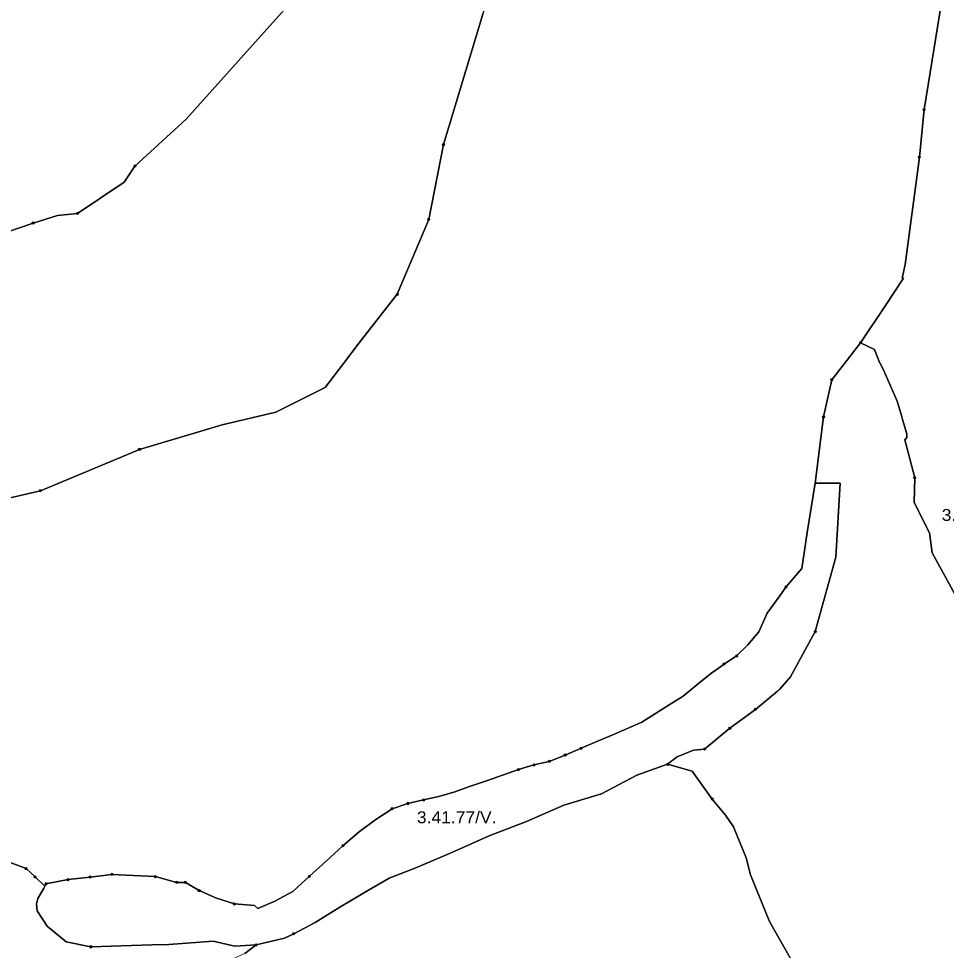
# Model space of a CAD drawing. Extents: x -650455 to -642254, y -1075222 to -1066610.
# Drawn here: x -646705 to -645923, y -1070494 to -1069709 of the extents above; entities that cross this region are included whole.
import ezdxf
from ezdxf.enums import TextEntityAlignment as Align

# ---------------------------------------------------------------- set-up
doc = ezdxf.new("R2010")
doc.units = 0
doc.header["$LTSCALE"] = 4
doc.header["$PDMODE"] = 32
doc.header["$PDSIZE"] = 2
for name, color, linetype, lineweight in [('1', 7, 'Continuous', 25), ('11', 7, 'Continuous', 13), ('12', 7, 'Continuous', 13), ('13', 7, 'Continuous', 13), ('14', 7, 'Continuous', 13), ('15', 7, 'Continuous', 13)]:
    doc.layers.add(name, color=color, linetype=linetype, lineweight=lineweight)
doc.layers.add('2', color=7, linetype='Continuous')

msp = doc.modelspace()

# ---------------------------------------------------------------- linework, layer by layer
at = {"layer": '1'}
for points in [[(-646385.5, -1069941.501), (-646359, -1069878.5), (-646346.5, -1069815.501), (-646313.5, -1069705.501), (-646295.5, -1069658.001), (-646241.5, -1069496.001), (-646193.5, -1069374.501), (-646167.5, -1069296), (-646158, -1069244.001), (-646160.5, -1069203.501), (-646183.5, -1069131.501), (-646202, -1069077.5), (-646206, -1069050.501), (-646201.5, -1069028), (-646192, -1069010.001), (-646156, -1068987.5), (-646026.5, -1068930.5), (-646006.5, -1068918.5), (-645969.5, -1068908.001), (-645923, -1068902.5)], [(-645960, -1069928), (-645957.5, -1069916.501), (-645945.5, -1069826), (-645941.5, -1069786), (-645925, -1069683.5), (-645928.5, -1069687.5), (-645921.5, -1069660.5), (-645908.5, -1069548.001), (-645886.5, -1069492.001), (-645856.5, -1069447.001), (-645698.133, -1069270.881), (-645694.109, -1069269.277), (-645694.125, -1069269.251), (-645637, -1069246.5), (-645633.75, -1069245.251), (-645633.394, -1069245.058), (-645602, -1069232.501), (-645598.374, -1069232.751)], [(-645925, -1069683.5), (-645941.5, -1069786), (-645945.5, -1069826), (-645957.5, -1069916.501), (-645960, -1069928), (-645958.773, -1069928.03), (-645974.12, -1069951.049), (-645994.986, -1069982.348), (-646008.715, -1070000), (-646019.329, -1070013.647), (-646026.284, -1070044.946), (-646033.24, -1070100.589), (-646040.195, -1070142.321), (-646044.529, -1070172.658), (-646057.984, -1070188.238), (-646063.155, -1070195.784), (-646073.776, -1070210.249), (-646080.764, -1070226.111), (-646090.127, -1070236.942), (-646099.491, -1070246.235), (-646110.112, -1070253.153), (-646121.432, -1070261.469), (-646133.032, -1070270.762), (-646144.631, -1070280.056), (-646156.231, -1070287.393), (-646167.83, -1070294.73), (-646179.43, -1070302.067), (-646203.747, -1070312.828), (-646217.164, -1070318.488), (-646230.58, -1070324.148), (-646243.996, -1070329.808), (-646257.413, -1070335.189), (-646270.27, -1070338.193), (-646283.407, -1070342.037), (-646296.823, -1070346.718), (-646310.24, -1070351.4)], [(-646850.869, -1069915.694), (-646849.651, -1069915.559), (-646838.507, -1069914.323), (-646823.887, -1069915.492), (-646812.777, -1069913.738), (-646803.42, -1069911.984), (-646794.649, -1069914.323), (-646784.708, -1069912.568), (-646771.258, -1069907.305), (-646745.528, -1069900.873), (-646716.29, -1069889.762), (-646692.314, -1069881.576), (-646671.847, -1069875.143), (-646654.889, -1069873.389), (-646615.709, -1069847.074), (-646606.5, -1069833.5), (-646563.5, -1069794), (-646468.5, -1069688)], [(-646468.5, -1069688), (-646563.5, -1069794), (-646606.5, -1069833.5), (-646615.709, -1069847.074), (-646654.889, -1069873.389), (-646671.847, -1069875.143), (-646692.314, -1069881.576), (-646716.29, -1069889.762), (-646745.528, -1069900.873), (-646771.258, -1069907.305), (-646784.708, -1069912.568), (-646794.649, -1069914.323), (-646803.42, -1069911.984), (-646812.777, -1069913.738), (-646823.887, -1069915.492), (-646838.507, -1069914.323), (-646849.651, -1069915.559), (-646850.869, -1069915.694)], [(-646313.5, -1069705.501), (-646346.5, -1069815.501), (-646359, -1069878.5), (-646385.5, -1069941.501), (-646417.5, -1069982.501), (-646430.839, -1070000), (-646446.211, -1070020.168), (-646487.943, -1070041.034), (-646533.153, -1070051.467), (-646602.706, -1070072.333), (-646686.17, -1070107.109), (-646776.589, -1070127.975)], [(-645892.146, -1070237.292), (-645934.808, -1070159.546), (-645937.054, -1070142.706), (-645949.965, -1070116.884), (-645949.403, -1070096.114), (-645957.823, -1070064.117), (-645955.946, -1070062.197), (-645955.946, -1070059.127), (-645958.753, -1070049.961), (-645961.472, -1070040.795), (-645964.191, -1070031.63), (-645968.226, -1070022.552), (-645972.085, -1070013.649), (-645976.12, -1070004.746), (-645978.592, -1070000), (-645978.839, -1069999.528), (-645983.4, -1069988.169), (-645994.986, -1069982.348), (-645974.12, -1069951.049), (-645958.773, -1069928.03), (-645960, -1069928)], [(-646776.589, -1070127.975), (-646686.17, -1070107.109), (-646602.706, -1070072.333), (-646533.153, -1070051.467), (-646487.943, -1070041.034), (-646446.211, -1070020.168), (-646430.839, -1070000), (-646417.5, -1069982.501), (-646385.5, -1069941.501)], [(-646071.795, -1070469.988), (-646087.776, -1070430.716), (-646091.516, -1070416.436), (-646102.056, -1070390.425), (-646108.856, -1070380.565), (-646120.077, -1070366.964), (-646137.077, -1070343.504), (-646157.707, -1070337.514), (-646149.487, -1070331.235), (-646135.809, -1070325.671), (-646126.536, -1070324.744), (-646105.207, -1070307.24), (-646083.647, -1070291.36), (-646065.1, -1070275.943), (-646064.049, -1070274.932), (-646063.394, -1070274.488), (-646054.106, -1070264.038), (-646033.24, -1070225.784), (-646015.851, -1070163.186), (-646012.374, -1070100.589), (-646033.24, -1070100.589), (-646026.284, -1070044.946), (-646019.329, -1070013.647), (-646008.715, -1070000), (-645994.986, -1069982.348), (-645983.4, -1069988.169), (-645978.839, -1069999.528), (-645978.592, -1070000), (-645976.12, -1070004.746), (-645972.085, -1070013.649), (-645968.226, -1070022.552), (-645964.191, -1070031.63), (-645961.472, -1070040.795), (-645958.753, -1070049.961), (-645955.946, -1070059.127), (-645955.946, -1070062.197), (-645957.823, -1070064.117), (-645949.403, -1070096.114), (-645949.965, -1070116.884), (-645937.054, -1070142.706)], [(-646503.1, -1070459.15), (-646488.566, -1070452.792), (-646473.612, -1070444.756), (-646459.497, -1070431.968), (-646445.382, -1070419.181), (-646431.267, -1070406.254), (-646417.291, -1070394.165), (-646403.456, -1070384.172), (-646389.899, -1070375.019), (-646376.483, -1070370.616), (-646363.346, -1070367.612), (-646350.349, -1070364.607), (-646337.072, -1070360.764), (-646323.656, -1070356.082), (-646310.24, -1070351.4), (-646296.823, -1070346.718), (-646283.407, -1070342.037), (-646270.27, -1070338.193), (-646257.413, -1070335.189), (-646243.996, -1070329.808), (-646230.58, -1070324.148), (-646217.164, -1070318.488), (-646203.747, -1070312.828), (-646179.43, -1070302.067), (-646167.83, -1070294.73), (-646156.231, -1070287.393), (-646144.631, -1070280.056), (-646133.032, -1070270.762), (-646121.432, -1070261.469), (-646110.112, -1070253.153), (-646099.491, -1070246.235), (-646090.127, -1070236.942), (-646080.764, -1070226.111), (-646073.776, -1070210.249), (-646063.155, -1070195.784), (-646057.984, -1070188.238), (-646044.529, -1070172.658), (-646040.195, -1070142.321), (-646033.24, -1070100.589), (-646012.374, -1070100.589)], [(-646012.374, -1070100.589), (-646015.851, -1070163.186), (-646033.24, -1070225.784), (-646054.106, -1070264.038), (-646063.394, -1070274.488), (-646064.049, -1070274.932), (-646065.1, -1070275.943), (-646083.647, -1070291.36), (-646105.207, -1070307.24), (-646126.536, -1070324.744), (-646135.809, -1070325.671), (-646149.487, -1070331.235), (-646157.707, -1070337.514)], [(-645937.054, -1070142.706), (-645934.808, -1070159.546), (-645892.146, -1070237.292), (-645883.165, -1070254.133), (-645864.64, -1070297.356), (-645851.729, -1070325.985), (-645836.012, -1070342.825), (-645812.997, -1070356.859), (-645785.491, -1070380.435), (-645768.65, -1070402.889), (-645763.626, -1070420.193)], [(-646157.707, -1070337.514), (-646183.567, -1070346.768), (-646213.473, -1070362.417), (-646245.003, -1070372.038), (-646276.532, -1070385.832), (-646308.062, -1070397.772), (-646339.359, -1070411.797), (-646369.729, -1070424.896), (-646392.217, -1070433.59), (-646413.082, -1070445.761), (-646433.947, -1070457.932), (-646454.58, -1070470.799), (-646472.663, -1070480.42), (-646480.546, -1070484.129), (-646504.412, -1070489.744), (-646522.293, -1070490.738), (-646540.7, -1070486.685), (-646578.106, -1070489.302), (-646592.291, -1070489.809), (-646643.714, -1070491.413), (-646664.401, -1070487.107), (-646680.613, -1070473.935), (-646689.056, -1070460.931), (-646689.394, -1070455.19), (-646688.291, -1070450.623), (-646683.243, -1070441.891), (-646682.529, -1070440.373), (-646681.566, -1070438.327), (-646662.839, -1070434.764), (-646644.391, -1070432.597), (-646625.944, -1070430.431), (-646607.636, -1070431.34), (-646589.328, -1070432.248), (-646571.44, -1070437.069), (-646564.033, -1070437.069), (-646552.433, -1070443.987), (-646537.759, -1070450.346), (-646522.666, -1070455.307), (-646505.895, -1070456.635), (-646503.1, -1070459.15)], [(-646513.93, -1070496.996), (-646504.412, -1070489.744), (-646480.546, -1070484.129), (-646472.663, -1070480.42), (-646454.58, -1070470.799), (-646433.947, -1070457.932), (-646413.082, -1070445.761), (-646392.217, -1070433.59), (-646369.729, -1070424.896), (-646339.359, -1070411.797), (-646308.062, -1070397.772), (-646276.532, -1070385.832), (-646245.003, -1070372.038), (-646213.473, -1070362.417), (-646183.567, -1070346.768), (-646157.707, -1070337.514), (-646137.077, -1070343.504), (-646120.077, -1070366.964), (-646108.856, -1070380.565), (-646102.056, -1070390.425), (-646091.516, -1070416.436), (-646087.776, -1070430.716), (-646071.795, -1070469.988), (-646053.095, -1070503.139)], [(-646310.24, -1070351.4), (-646323.656, -1070356.082), (-646337.072, -1070360.764), (-646350.349, -1070364.607), (-646363.346, -1070367.612), (-646376.483, -1070370.616), (-646389.899, -1070375.019), (-646403.456, -1070384.172), (-646417.291, -1070394.165), (-646431.267, -1070406.254), (-646445.382, -1070419.181), (-646459.497, -1070431.968), (-646473.612, -1070444.756), (-646488.566, -1070452.792), (-646503.1, -1070459.15), (-646505.895, -1070456.635), (-646522.666, -1070455.307), (-646537.759, -1070450.346), (-646552.433, -1070443.987), (-646564.033, -1070437.069), (-646571.44, -1070437.069), (-646589.328, -1070432.248), (-646607.636, -1070431.34), (-646625.944, -1070430.431), (-646644.391, -1070432.597), (-646662.839, -1070434.764), (-646681.566, -1070438.327), (-646682.529, -1070440.373), (-646690.65, -1070432.527), (-646698.336, -1070425.54), (-646716.085, -1070418.622)], [(-646895.25, -1070424.491), (-646877.361, -1070423.583), (-646859.613, -1070422.675), (-646841.444, -1070420.229), (-646823.276, -1070420.998), (-646805.248, -1070421.766), (-646787.22, -1070420.299), (-646769.192, -1070417.294), (-646751.583, -1070414.289), (-646733.694, -1070416.456), (-646716.085, -1070418.622), (-646698.336, -1070425.54), (-646690.65, -1070432.527), (-646682.529, -1070440.373)], [(-646682.529, -1070440.373), (-646683.243, -1070441.891), (-646688.291, -1070450.623), (-646689.394, -1070455.19), (-646689.056, -1070460.931), (-646680.613, -1070473.935), (-646664.401, -1070487.107), (-646643.714, -1070491.413), (-646592.291, -1070489.809), (-646578.106, -1070489.302), (-646540.7, -1070486.685), (-646522.293, -1070490.738), (-646504.412, -1070489.744), (-646513.93, -1070496.996)], [(-645920.242, -1070713.679), (-645927.962, -1070711.588), (-645950.317, -1070694.38), (-645965.032, -1070672.106), (-645972.912, -1070658.757), (-645982.884, -1070639.297), (-645992.731, -1070624.604), (-645999.333, -1070608.761), (-646000.735, -1070603.916), (-646002.692, -1070598.86), (-646005.067, -1070591.608), (-646007.731, -1070584.143), (-646009.999, -1070577.784), (-646016.721, -1070567.029), (-646017.857, -1070565.514), (-646032.694, -1070537.65), (-646053.095, -1070503.139), (-646071.795, -1070469.988)]]:
    msp.add_lwpolyline(points, dxfattribs=at)
at = {"layer": '11'}
for p, q in [((-646257.413, -1070335.189), (-646243.996, -1070329.808)), ((-646243.996, -1070329.808), (-646230.58, -1070324.148)), ((-646270.27, -1070338.193), (-646257.413, -1070335.189)), ((-646698.336, -1070425.54), (-646690.65, -1070432.527)), ((-646644.391, -1070432.597), (-646625.944, -1070430.431)), ((-646589.328, -1070432.248), (-646571.44, -1070437.069)), ((-646662.839, -1070434.764), (-646644.391, -1070432.597)), ((-646571.44, -1070437.069), (-646564.033, -1070437.069)), ((-646564.033, -1070437.069), (-646552.433, -1070443.987))]:
    msp.add_line(p, q, dxfattribs=at)
for points in [[(-645941.5, -1069786), (-645925, -1069683.5), (-645928.5, -1069687.5), (-645921.5, -1069660.5), (-645908.5, -1069548.001), (-645886.5, -1069492.001), (-645856.5, -1069447.001), (-645698.133, -1069270.881), (-645695.195, -1069267.614), (-645695.188, -1069267.626), (-645687, -1069258.5), (-645636.5, -1069209.001), (-645431, -1069051.5), (-645370.25, -1069009.125)], [(-646158, -1069244.001), (-646167.5, -1069296), (-646193.5, -1069374.501), (-646241.5, -1069496.001), (-646295.5, -1069658.001), (-646313.5, -1069705.501), (-646346.5, -1069815.501), (-646359, -1069878.5)], [(-646606.5, -1069833.5), (-646563.5, -1069794), (-646468.5, -1069688), (-646431, -1069636.5)], [(-645994.986, -1069982.348), (-645974.12, -1069951.049), (-645958.773, -1069928.03), (-645960, -1069928), (-645957.5, -1069916.501), (-645945.5, -1069826), (-645941.5, -1069786)], [(-646692.314, -1069881.576), (-646671.847, -1069875.143), (-646654.889, -1069873.389), (-646615.709, -1069847.074), (-646606.5, -1069833.5)], [(-646803.42, -1069911.984), (-646794.649, -1069914.323), (-646784.708, -1069912.568), (-646771.258, -1069907.305), (-646745.528, -1069900.873), (-646716.29, -1069889.762), (-646692.314, -1069881.576)], [(-646359, -1069878.5), (-646385.5, -1069941.501), (-646417.5, -1069982.501), (-646430.839, -1070000), (-646446.211, -1070020.168), (-646487.943, -1070041.034), (-646533.153, -1070051.467), (-646602.706, -1070072.333), (-646686.17, -1070107.109)], [(-646019.329, -1070013.647), (-646008.715, -1070000), (-645994.986, -1069982.348)], [(-646057.984, -1070188.238), (-646044.529, -1070172.658), (-646040.195, -1070142.321), (-646033.24, -1070100.589), (-646026.284, -1070044.946), (-646019.329, -1070013.647)], [(-646686.17, -1070107.109), (-646776.589, -1070127.975), (-646839.187, -1070117.542)], [(-646099.491, -1070246.235), (-646090.127, -1070236.942), (-646080.764, -1070226.111), (-646073.776, -1070210.249), (-646063.155, -1070195.784), (-646057.984, -1070188.238)], [(-646230.58, -1070324.148), (-646217.164, -1070318.488), (-646203.747, -1070312.828), (-646179.43, -1070302.067), (-646167.83, -1070294.73), (-646156.231, -1070287.393), (-646144.631, -1070280.056), (-646133.032, -1070270.762), (-646121.432, -1070261.469), (-646110.112, -1070253.153), (-646099.491, -1070246.235)], [(-646363.346, -1070367.612), (-646350.349, -1070364.607), (-646337.072, -1070360.764), (-646323.656, -1070356.082), (-646310.24, -1070351.4), (-646296.823, -1070346.718), (-646283.407, -1070342.037), (-646270.27, -1070338.193)], [(-646552.433, -1070443.987), (-646537.759, -1070450.346), (-646522.666, -1070455.307), (-646505.895, -1070456.635), (-646503.1, -1070459.15), (-646488.566, -1070452.792), (-646473.612, -1070444.756), (-646459.497, -1070431.968), (-646445.382, -1070419.181), (-646431.267, -1070406.254), (-646417.291, -1070394.165), (-646403.456, -1070384.172), (-646389.899, -1070375.019), (-646376.483, -1070370.616), (-646363.346, -1070367.612)], [(-646948.775, -1070423.304), (-646930.747, -1070423.513), (-646912.999, -1070424.002), (-646895.25, -1070424.491), (-646877.361, -1070423.583), (-646859.613, -1070422.675), (-646841.444, -1070420.229), (-646823.276, -1070420.998), (-646805.248, -1070421.766), (-646787.22, -1070420.299), (-646769.192, -1070417.294), (-646751.583, -1070414.289), (-646733.694, -1070416.456), (-646716.085, -1070418.622), (-646698.336, -1070425.54)], [(-646625.944, -1070430.431), (-646607.636, -1070431.34), (-646589.328, -1070432.248)], [(-646690.65, -1070432.527), (-646682.529, -1070440.373), (-646681.566, -1070438.327), (-646662.839, -1070434.764)]]:
    msp.add_lwpolyline(points, dxfattribs=at)
for p in [(-645941.5, -1069786), (-646606.5, -1069833.5), (-646692.314, -1069881.576), (-646359, -1069878.5), (-645994.986, -1069982.348), (-646019.329, -1070013.647), (-646686.17, -1070107.109), (-646057.984, -1070188.238), (-646099.491, -1070246.235), (-646243.996, -1070329.808), (-646230.58, -1070324.148), (-646270.27, -1070338.193), (-646257.413, -1070335.189), (-646363.346, -1070367.612), (-646698.336, -1070425.54), (-646690.65, -1070432.527), (-646644.391, -1070432.597), (-646625.944, -1070430.431), (-646589.328, -1070432.248), (-646662.839, -1070434.764), (-646571.44, -1070437.069), (-646564.033, -1070437.069), (-646552.433, -1070443.987)]:
    msp.add_point(p, dxfattribs=at)
at = {"layer": '12'}
for points in [[(-645994.986, -1069982.348), (-646008.715, -1070000), (-646019.329, -1070013.647), (-646026.284, -1070044.946)], [(-645892.146, -1070237.292), (-645934.808, -1070159.546), (-645937.054, -1070142.706), (-645949.965, -1070116.884), (-645949.403, -1070096.114), (-645957.823, -1070064.117), (-645955.946, -1070062.197), (-645955.946, -1070059.127), (-645958.753, -1070049.961), (-645961.472, -1070040.795), (-645964.191, -1070031.63), (-645968.226, -1070022.552), (-645972.085, -1070013.649), (-645976.12, -1070004.746), (-645978.592, -1070000), (-645978.839, -1069999.528), (-645983.4, -1069988.169), (-645994.986, -1069982.348)], [(-646026.284, -1070044.946), (-646033.24, -1070100.589), (-646012.374, -1070100.589), (-646015.851, -1070163.186), (-646033.24, -1070225.784)], [(-646033.24, -1070225.784), (-646054.106, -1070264.038), (-646063.394, -1070274.488), (-646064.049, -1070274.932), (-646065.1, -1070275.943), (-646083.647, -1070291.36)], [(-646083.647, -1070291.36), (-646105.207, -1070307.24), (-646126.536, -1070324.744), (-646135.809, -1070325.671), (-646149.487, -1070331.235), (-646157.707, -1070337.514), (-646137.077, -1070343.504), (-646120.077, -1070366.964), (-646108.856, -1070380.565), (-646102.056, -1070390.425), (-646091.516, -1070416.436), (-646087.776, -1070430.716), (-646071.795, -1070469.988), (-646053.095, -1070503.139), (-646032.694, -1070537.65), (-646017.857, -1070565.514), (-646016.721, -1070567.029), (-646009.999, -1070577.784), (-646007.731, -1070584.143), (-646005.067, -1070591.608), (-646002.692, -1070598.86), (-646000.735, -1070603.916)], [(-646157.707, -1070337.514), (-646183.567, -1070346.768), (-646213.473, -1070362.417), (-646245.003, -1070372.038), (-646276.532, -1070385.832), (-646308.062, -1070397.772), (-646339.359, -1070411.797), (-646369.729, -1070424.896), (-646392.217, -1070433.59), (-646413.082, -1070445.761), (-646433.947, -1070457.932), (-646454.58, -1070470.799), (-646472.663, -1070480.42), (-646480.546, -1070484.129), (-646504.412, -1070489.744)], [(-646120.077, -1070366.964), (-646137.077, -1070343.504), (-646157.707, -1070337.514)], [(-646014.913, -1070609.041), (-646008.134, -1070603.149), (-646004.664, -1070600.284), (-646002.692, -1070598.86), (-646005.067, -1070591.608), (-646007.731, -1070584.143), (-646009.999, -1070577.784), (-646016.721, -1070567.029), (-646017.857, -1070565.514), (-646032.694, -1070537.65), (-646053.095, -1070503.139), (-646071.795, -1070469.988), (-646087.776, -1070430.716), (-646091.516, -1070416.436), (-646102.056, -1070390.425), (-646108.856, -1070380.565), (-646120.077, -1070366.964)], [(-646504.412, -1070489.744), (-646513.93, -1070496.996), (-646514.69, -1070497.343), (-646529.926, -1070504.299)]]:
    msp.add_lwpolyline(points, dxfattribs=at)
for p in [(-645994.986, -1069982.348), (-646026.284, -1070044.946), (-646033.24, -1070225.784), (-646083.647, -1070291.36), (-646157.707, -1070337.514), (-646120.077, -1070366.964), (-646504.412, -1070489.744)]:
    msp.add_point(p, dxfattribs=at)
at = {"layer": '13'}
for points in [[(-646410.5, -1069578.5), (-646414.5, -1069601.001), (-646431, -1069636.5), (-646468.5, -1069688), (-646563.5, -1069794), (-646606.5, -1069833.5), (-646615.709, -1069847.074), (-646654.889, -1069873.389)], [(-646346.5, -1069815.501), (-646313.5, -1069705.501), (-646295.5, -1069658.001)], [(-646385.5, -1069941.501), (-646359, -1069878.5), (-646346.5, -1069815.501)], [(-646692.314, -1069881.576), (-646716.29, -1069889.762), (-646745.528, -1069900.873), (-646771.258, -1069907.305), (-646784.708, -1069912.568), (-646794.649, -1069914.323), (-646803.42, -1069911.984), (-646812.777, -1069913.738), (-646823.887, -1069915.492), (-646838.507, -1069914.323), (-646849.651, -1069915.559), (-646850.869, -1069915.694), (-646940.039, -1069905.405), (-647009.592, -1069888.017), (-647081.803, -1069875.123), (-647157.209, -1069869.737), (-647213.764, -1069868.391), (-647184.14, -1069896.668), (-647167.981, -1069939.757)], [(-646654.889, -1069873.389), (-646671.847, -1069875.143), (-646692.314, -1069881.576)], [(-646602.706, -1070072.333), (-646533.153, -1070051.467), (-646487.943, -1070041.034), (-646446.211, -1070020.168), (-646430.839, -1070000), (-646417.5, -1069982.501), (-646385.5, -1069941.501)], [(-646776.589, -1070127.975), (-646686.17, -1070107.109), (-646602.706, -1070072.333)]]:
    msp.add_lwpolyline(points, dxfattribs=at)
for p in [(-646346.5, -1069815.501), (-646654.889, -1069873.389), (-646692.314, -1069881.576), (-646385.5, -1069941.501), (-646602.706, -1070072.333)]:
    msp.add_point(p, dxfattribs=at)
at = {"layer": '14'}
msp.add_lwpolyline([(-646514.69, -1070497.343), (-646513.93, -1070496.996), (-646504.412, -1070489.744), (-646522.293, -1070490.738), (-646540.7, -1070486.685), (-646578.106, -1070489.302), (-646592.291, -1070489.809), (-646643.714, -1070491.413), (-646664.401, -1070487.107), (-646680.613, -1070473.935), (-646689.056, -1070460.931), (-646689.394, -1070455.19), (-646688.291, -1070450.623), (-646683.243, -1070441.891), (-646682.529, -1070440.373), (-646690.65, -1070432.527), (-646698.336, -1070425.54), (-646716.085, -1070418.622), (-646733.694, -1070416.456), (-646751.583, -1070414.289), (-646769.192, -1070417.294)], dxfattribs=at)
at = {"layer": '15'}
for p, q in [((-646126.536, -1070324.744), (-646105.207, -1070307.24)), ((-646376.483, -1070370.616), (-646389.899, -1070375.019)), ((-646662.839, -1070434.764), (-646681.566, -1070438.327))]:
    msp.add_line(p, q, dxfattribs=at)
for points in [[(-645925, -1069683.5), (-645941.5, -1069786), (-645945.5, -1069826)], [(-645945.5, -1069826), (-645957.5, -1069916.501), (-645960, -1069928), (-645958.773, -1069928.03), (-645974.12, -1069951.049), (-645994.986, -1069982.348)], [(-645994.986, -1069982.348), (-645983.4, -1069988.169), (-645978.839, -1069999.528), (-645978.592, -1070000), (-645976.12, -1070004.746), (-645972.085, -1070013.649), (-645968.226, -1070022.552), (-645964.191, -1070031.63), (-645961.472, -1070040.795), (-645958.753, -1070049.961), (-645955.946, -1070059.127), (-645955.946, -1070062.197), (-645957.823, -1070064.117), (-645949.403, -1070096.114)], [(-646105.207, -1070307.24), (-646083.647, -1070291.36), (-646065.1, -1070275.943), (-646064.049, -1070274.932), (-646063.394, -1070274.488), (-646054.106, -1070264.038), (-646033.24, -1070225.784), (-646015.851, -1070163.186), (-646012.374, -1070100.589), (-646033.24, -1070100.589), (-646040.195, -1070142.321), (-646044.529, -1070172.658), (-646057.984, -1070188.238), (-646063.155, -1070195.784), (-646073.776, -1070210.249), (-646080.764, -1070226.111), (-646090.127, -1070236.942), (-646099.491, -1070246.235), (-646110.112, -1070253.153)], [(-645949.403, -1070096.114), (-645949.965, -1070116.884), (-645937.054, -1070142.706), (-645934.808, -1070159.546), (-645892.146, -1070237.292), (-645883.165, -1070254.133), (-645864.64, -1070297.356), (-645851.729, -1070325.985), (-645836.012, -1070342.825), (-645812.997, -1070356.859), (-645785.491, -1070380.435), (-645768.65, -1070402.889), (-645763.626, -1070420.193), (-645741.986, -1070441.834), (-645729.814, -1070460.091), (-645712.054, -1070466.012), (-645711, -1070465.5), (-645695.5, -1070468.001), (-645688.022, -1070470.362)], [(-646110.112, -1070253.153), (-646121.432, -1070261.469), (-646133.032, -1070270.762), (-646144.631, -1070280.056), (-646156.231, -1070287.393), (-646167.83, -1070294.73), (-646179.43, -1070302.067), (-646203.747, -1070312.828), (-646217.164, -1070318.488), (-646230.58, -1070324.148), (-646243.996, -1070329.808), (-646257.413, -1070335.189), (-646270.27, -1070338.193), (-646283.407, -1070342.037)], [(-646213.473, -1070362.417), (-646183.567, -1070346.768), (-646157.707, -1070337.514), (-646149.487, -1070331.235), (-646135.809, -1070325.671), (-646126.536, -1070324.744)], [(-646283.407, -1070342.037), (-646296.823, -1070346.718), (-646310.24, -1070351.4), (-646323.656, -1070356.082), (-646337.072, -1070360.764), (-646350.349, -1070364.607), (-646363.346, -1070367.612), (-646376.483, -1070370.616)], [(-646472.663, -1070480.42), (-646454.58, -1070470.799), (-646433.947, -1070457.932), (-646413.082, -1070445.761), (-646392.217, -1070433.59), (-646369.729, -1070424.896), (-646339.359, -1070411.797), (-646308.062, -1070397.772), (-646276.532, -1070385.832), (-646245.003, -1070372.038), (-646213.473, -1070362.417)], [(-646389.899, -1070375.019), (-646403.456, -1070384.172), (-646417.291, -1070394.165), (-646431.267, -1070406.254)], [(-646431.267, -1070406.254), (-646445.382, -1070419.181), (-646459.497, -1070431.968)], [(-646625.944, -1070430.431), (-646644.391, -1070432.597), (-646662.839, -1070434.764)], [(-646571.44, -1070437.069), (-646589.328, -1070432.248), (-646607.636, -1070431.34), (-646625.944, -1070430.431)], [(-646459.497, -1070431.968), (-646473.612, -1070444.756), (-646488.566, -1070452.792), (-646503.1, -1070459.15), (-646505.895, -1070456.635), (-646522.666, -1070455.307)], [(-646681.566, -1070438.327), (-646682.529, -1070440.373), (-646683.243, -1070441.891), (-646688.291, -1070450.623), (-646689.394, -1070455.19), (-646689.056, -1070460.931), (-646680.613, -1070473.935), (-646664.401, -1070487.107), (-646643.714, -1070491.413)], [(-646522.666, -1070455.307), (-646537.759, -1070450.346), (-646552.433, -1070443.987), (-646564.033, -1070437.069), (-646571.44, -1070437.069)], [(-646643.714, -1070491.413), (-646592.291, -1070489.809), (-646578.106, -1070489.302), (-646540.7, -1070486.685), (-646522.293, -1070490.738), (-646504.412, -1070489.744), (-646480.546, -1070484.129), (-646472.663, -1070480.42)]]:
    msp.add_lwpolyline(points, dxfattribs=at)
for p in [(-645945.5, -1069826), (-645994.986, -1069982.348), (-645949.403, -1070096.114), (-646110.112, -1070253.153), (-646105.207, -1070307.24), (-646126.536, -1070324.744), (-646283.407, -1070342.037), (-646376.483, -1070370.616), (-646389.899, -1070375.019), (-646431.267, -1070406.254), (-646625.944, -1070430.431), (-646459.497, -1070431.968), (-646681.566, -1070438.327), (-646662.839, -1070434.764), (-646571.44, -1070437.069), (-646522.666, -1070455.307), (-646472.663, -1070480.42), (-646643.714, -1070491.413)]:
    msp.add_point(p, dxfattribs=at)

# ---------------------------------------------------------------- texts
at = {"layer": '2', "width": 1.1}
for p in [(-645893.136, -1070132.488), (-646335.406, -1070387.24)]:
    msp.add_text('3.41.77/V.', height=10, dxfattribs=at).set_placement(p, align=Align.CENTER)

doc.saveas('drawing.dxf')
